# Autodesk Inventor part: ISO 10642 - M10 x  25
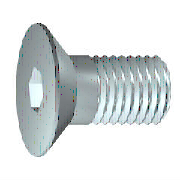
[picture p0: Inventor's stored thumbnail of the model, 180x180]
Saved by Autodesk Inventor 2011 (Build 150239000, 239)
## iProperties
Created: 2010-02
Part Number: ISO 10642 - M10 x  25
Material: Steel
Description: Hexagon Socket Countersunk Head Screw-1 - Product grade A
Document SubType Name: Modeling
Standard: ISO 10642
Designer: 129877
Standard Revision: Second edition 2004-03-01
Standards Organization: ISO
Language: en-US
Size Designation: M10 x  25
Categories: <MemberInstance><Categories><Category DisplayName="Fasteners" InternalName="e4da775c-781d-43d5-af7c-5136215cf5a6" Mnemonic="FSTN"><Category DisplayName="Bolts"
Density: 7.85 g/cm^3
Mass: 20.1675 g
Surface Area: 14.3186 cm^2
Volume: 2.5691 cm^3
IsCustomPart: 0
Author: 129877
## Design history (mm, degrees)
body "Solid1"
workplane "Work Plane1"
revolve "Body" stored, may be unused: angle "d13" = 90 deg
sketch "Sketch2"
  geometry: L1 (0, -13.454)-(0, 13.454) reference; L2 (-13.454, 0)-(13.454, 0) reference; L3 (3.464, 0)-(1.732, -3); L4 (1.732, -3)-(-1.732, -3); L5 (-1.732, -3)-(-3.464, 0); L6 (-3.464, 0)-(-1.732, 3); L7 (-1.732, 3)-(1.732, 3); L8 (1.732, 3)-(3.464, 0); A1 r 3.464 centre (0, 0) between (0, 3.464) and (3.464, 0) reference; 2 further points
  constraints: 12 end point, 2 coincident, 2 point on circle, 2 point on line, 12 other
extrude "Slot" join sketch "Sketch2" taper "d14" = 0 deg; stored distance "d30" = 10
feature "Thread" dims "d15" = 14 (= GEL), "d16" = 0
chamfer "Chamfer1" distance "d17" = 0.92018 (= -0.5 x SPD + 0.5 x GD); stored, may be unused: second distance "d18" = 0.92018 (= GUL), angle "d39" = 45 deg
sketch "Sketch1"
  geometry: L1 (25, 0)-(25, 5); L2 (25, 5)-(11, 5); L3 (11, 5)-(10.08, 5); L4 (0, 9.61)-(0, 3.464); L5 (0, 3.464)-(4.18, 3.464); L6 (4.18, 3.464)-(6.18, 0); L7 (6.18, 0)-(25, 0); L8 (0, 9.61)-(1.59, 9.61); L9 (1.59, 9.61)-(6.2, 5); L10 (10.08, 5)-(6.2, 5); L11 (11, 5)-(6.2, 5); L12 (6.2, 5)-(6.2, 5); L13 (-5, 0)-(30, 0) reference; L14 (0, -1.922)-(0, 11.532) reference
  constraints: 24 end point, 4 collinear, 3 parallel
  dimensions: "d0" = 25 distance between parallel lines of L4 L1 (= NLG); "d1" = 14 distance from line of L2.end L1 (= GEL); "d2" = 4.18 distance from line of L5.end L4 (= INTI); "d3" = 10 diameter of L2 L7 (= GD); "d6" = 6.2 distance from line of L9.end L4 (= KOH); "d7" = 45 deg angle of L9 L7 (= 0.5 x SEWI); "d8" = 6.9282 diameter of L5 L7 (= 1.1547 x SW); "d9" = 60 deg angle of L6 L7; "d10" = 19.22 diameter of L8 L7 (= KOD); "d11" = 10 diameter of L10 L7 (= BDM); "d12" = 0.92018 distance of L3.end L2.end (= GAL)
other parameters: "NLG" = 25 [user parameter; used in 1 equation term], "INTI" = 4.18 [user parameter; used in 1 equation term], "GEL" = 14 [user parameter; used in 2 equation terms], "GAL" = 0.92018 (= 0.61345 x PTC) [user parameter; used in 1 equation term], "KOH" = 6.2 [user parameter; used in 1 equation term], "KOD" = 19.22 [user parameter; used in 1 equation term], "GUL" = 0.92018 (= 0.61345 x PTC) [user parameter; used in 1 equation term], "SPD" = 8.15965 (= NND - 1.2269 x PTC) [user parameter; used in 1 equation term], "BDM" = 10 (= NND) [user parameter; used in 1 equation term], "GD" = 10 (= NND) [user parameter; used in 2 equation terms], "SEWI" = 90 deg [user parameter; used in 1 equation term], "d20" = 0, "SW" = 6 [user parameter; used in 1 equation term], "d43" = 0, "d44" = 0, "TOA" = 30 deg [user parameter], "GD1" = 8.15965 (= THREADDIA - 1.2269 x PTC) [user parameter], "EPV" = 11.2 [user parameter], "TPU" = 6.66667 (computed from PTC) [user parameter], "PTC" = 1.5 [user parameter; used in 5 equation terms], "E0" = 6.93 [user parameter], "THREADDESC" = 12.345 [user parameter]
